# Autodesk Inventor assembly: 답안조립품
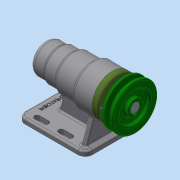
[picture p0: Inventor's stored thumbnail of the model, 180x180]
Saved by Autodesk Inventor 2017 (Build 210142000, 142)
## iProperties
Part Number: 답안조립품
Material: 일반
Document SubType Name: Assembly
Designer: MRC
Author: MRC
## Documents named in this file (12)
- C:\Users\MRC\Desktop\711009V1001\답안조립품.iam
- C:\Users\MRC\Desktop\711009V1001\본체.ipt
- C:\Users\MRC\Desktop\711009V1001\V벨트풀리.ipt
- C:\Users\MRC\Desktop\711009V1001\멈춤나사 M3.ipt
- C:\Users\MRC\Desktop\711009V1001\베어링 6004.ipt
- C:\Users\MRC\Desktop\711009V1001\베어링 51202.ipt
- C:\Users\MRC\Desktop\711009V1001\볼트 M4.ipt
- C:\Users\MRC\Desktop\711009V1001\어댑터슬리브.ipt
- C:\Users\MRC\Desktop\711009V1001\오일 실 20x35x7.ipt
- C:\Users\MRC\Desktop\711009V1001\축.ipt
- C:\Users\MRC\Desktop\711009V1001\커버.ipt
- C:\Users\MRC\Desktop\711009V1001\키 5x5.ipt
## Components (1 placed, 1 different names)
1. V벨트풀리:1
